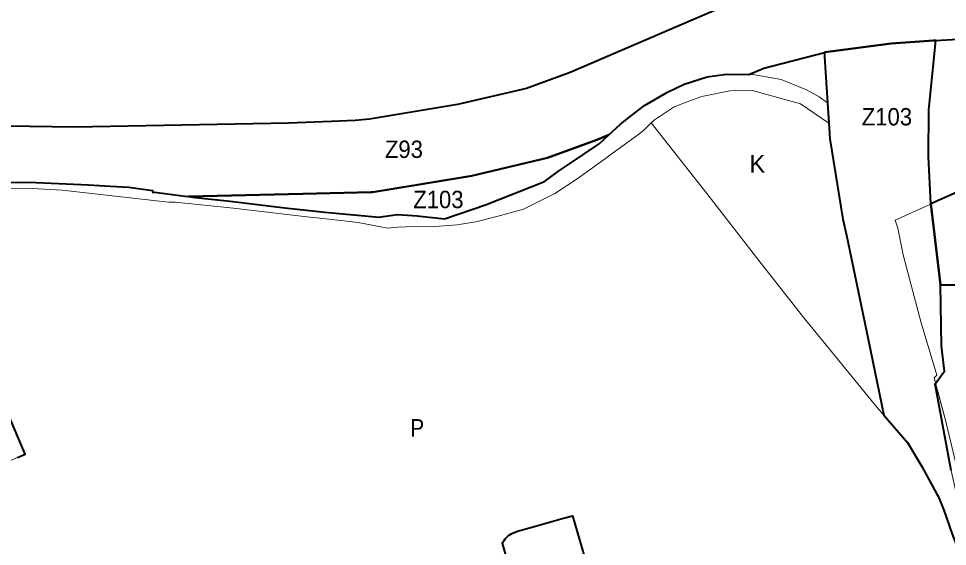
# Model space of a CAD drawing. Extents: x -650276 to -642489, y -1074425 to -1066658.
# Drawn here: x -649154 to -647871, y -1069752 to -1069023 of the extents above; entities that cross this region are included whole.
import ezdxf

# ---------------------------------------------------------------- set-up
doc = ezdxf.new("R2010")
doc.units = 0
doc.header["$LTSCALE"] = 9.6
for name, color, linetype, lineweight in [('1', 7, 'Continuous', 13), ('43', 7, 'Continuous', 13), ('44', 7, 'Continuous', 40), ('45', 7, 'Continuous', 40), ('47', 7, 'Continuous', 13), ('60', 7, 'Continuous', 35)]:
    doc.layers.add(name, color=color, linetype=linetype, lineweight=lineweight)

msp = doc.modelspace()

# ---------------------------------------------------------------- linework, layer by layer
at = {"layer": '1'}
for points in [[(-647858.44, -1069749.43), (-647875.82, -1069701.85), (-647883.51, -1069682.71), (-647885.34, -1069679.38), (-647906.16, -1069641.48), (-647925.99, -1069608.57), (-647967.53, -1069559.94), (-648068.71, -1069436.57), (-648127.77, -1069361.38), (-648203.01, -1069264.73), (-648280.1, -1069166.97), (-648290.39, -1069177.69), (-648298.85, -1069183.86), (-648338.87, -1069213.04), (-648342.93, -1069216), (-648352.75, -1069223.16), (-648381.96, -1069244.46), (-648412.97, -1069264.69), (-648456.09, -1069286.03), (-648493.11, -1069296.38), (-648522.23, -1069303.81), (-648547.96, -1069308.01), (-648578.69, -1069310.32), (-648618.32, -1069310.7), (-648629.16, -1069310.91), (-648643.83, -1069312.66), (-648684.39, -1069304.67), (-648724.82, -1069299.92), (-648741.58, -1069298.16), (-648755.56, -1069296.7), (-648856.68, -1069285.01), (-648937.2, -1069276.37), (-648945.96, -1069276.64), (-648959.11, -1069275.13), (-649093.48, -1069259.74), (-649142.11, -1069257.07), (-649181.7, -1069258.52)], [(-647858.37, -1069263.03), (-647942.68, -1069301.34), (-647939.14, -1069312.22), (-647931.96, -1069349.21), (-647920.91, -1069391.06), (-647906.89, -1069443.38), (-647885.3, -1069515.57), (-647889.22, -1069519.32), (-647873.43, -1069577.87), (-647852.44, -1069664.03)], [(-649184.1, -1069532.2), (-649144.57, -1069624.6), (-649241.11, -1069665.9)]]:
    msp.add_lwpolyline(points, dxfattribs=at)
at = {"layer": '44'}
for points in [[(-648156.739, -1068996.273), (-648392.002, -1069097.554), (-648451.865, -1069119.456), (-648547.243, -1069141.81), (-648668.959, -1069161.838), (-648688.912, -1069163.603), (-648721.315, -1069164.952), (-648781.015, -1069167.44), (-649076.02, -1069172.683), (-649169.781, -1069171.432)], [(-648040.456, -1069069.483), (-648039.666, -1069069.279), (-647948.18, -1069057.276)], [(-647948.18, -1069057.276), (-648039.666, -1069069.279), (-648040.456, -1069069.483)], [(-647948.18, -1069057.276), (-647889.927, -1069053.218), (-647886.615, -1069053.052)], [(-647886.615, -1069053.052), (-647889.927, -1069053.218), (-647948.18, -1069057.276)], [(-647887.087, -1069527.229), (-647878.73, -1069515.45), (-647874.75, -1069509.84), (-647878.93, -1069475.09), (-647880.326, -1069390.832), (-647893.553, -1069279.021), (-647896.67, -1069213.573), (-647896.362, -1069149.171), (-647886.615, -1069053.052)], [(-647886.615, -1069053.052), (-647856.541, -1069051.548), (-647756.441, -1069053.207), (-647708.401, -1069056.275), (-647511.94, -1069076.703), (-647426.417, -1069084.624), (-647344.902, -1069091.02), (-647270.522, -1069094.255), (-647197.498, -1069094.255), (-647123.648, -1069091.043), (-647065.688, -1069087.73)], [(-648665.007, -1069262.694), (-648527.693, -1069239.938), (-648423.173, -1069215.44), (-648354.978, -1069190.492), (-648338.523, -1069183.389), (-648322.14, -1069168.56), (-648306.83, -1069156.57), (-648289.25, -1069142.79), (-648257.5, -1069124.41), (-648234.22, -1069113.6), (-648202.46, -1069103.3), (-648175.65, -1069099.64), (-648144.866, -1069099.987), (-648124.327, -1069091.181), (-648040.705, -1069069.547), (-648040.456, -1069069.483)], [(-648040.456, -1069069.483), (-648040.537, -1069075.531), (-648036.291, -1069139.458), (-648034.421, -1069167.61)], [(-648034.421, -1069167.61), (-648033, -1069189), (-648015, -1069300), (-648010.092, -1069322.087), (-647980.331, -1069465.915), (-647958.34, -1069570.699), (-647925.99, -1069608.57)], [(-648526.15, -1069286.21), (-648508.95, -1069280.01), (-648427.08, -1069247.75), (-648407.73, -1069233.88), (-648389.91, -1069221.86), (-648355.81, -1069198.88), (-648351.77, -1069195.88), (-648338.523, -1069183.389), (-648354.978, -1069190.492)], [(-648354.978, -1069190.492), (-648423.173, -1069215.44), (-648527.693, -1069239.938), (-648652.716, -1069260.657)], [(-649165.62, -1069249.43), (-649139.63, -1069248.73), (-649056.95, -1069252.55), (-649026.955, -1069254.366), (-649001.3, -1069255.92), (-648968.49, -1069260.36), (-648968.05, -1069263.06), (-648965.8, -1069262.75), (-648937.91, -1069266.51), (-648924.13, -1069268.21), (-648918.889, -1069268.875)], [(-648918.889, -1069268.875), (-648761.189, -1069265.035), (-648666.827, -1069262.738), (-648665.007, -1069262.694)], [(-648666.827, -1069262.738), (-648761.189, -1069265.035), (-648918.889, -1069268.875), (-648909.86, -1069270.02), (-648861.49, -1069275.34), (-648785.92, -1069284.2), (-648730.66, -1069290.43), (-648730.66, -1069290.43), (-648655.53, -1069297.18), (-648650.06, -1069296.39), (-648636.85, -1069294.49)], [(-648652.716, -1069260.657), (-648665.007, -1069262.694), (-648666.827, -1069262.738)], [(-648636.85, -1069294.49), (-648630.82, -1069293.63), (-648609.425, -1069295.033), (-648603.228, -1069295.53), (-648565.18, -1069299.46), (-648526.15, -1069286.21)], [(-647865.69, -1069647.32), (-647887.649, -1069528.021), (-647887.087, -1069527.229)], [(-647925.99, -1069608.57), (-647906.16, -1069641.48), (-647885.665, -1069678.788), (-647885.663, -1069678.794), (-647883.51, -1069682.71), (-647875.82, -1069701.85)], [(-647875.82, -1069701.85), (-647864.19, -1069735.12), (-647858.44, -1069749.43), (-647852.63, -1069775.7), (-647850.66, -1069785.74), (-647849.165, -1069793.367), (-647843.74, -1069817.63), (-647841.402, -1069792.351)]]:
    msp.add_lwpolyline(points, dxfattribs=at)
msp.add_lwpolyline([(-647860.52, -1069390.72), (-647848.24, -1069390.65), (-647845.25, -1069390.07), (-647843.41, -1069389.23), (-647841.81, -1069387.99), (-647840.42, -1069386.51), (-647839.4, -1069384.73), (-647838.79, -1069382.86), (-647836.2, -1069362.68), (-647832.29, -1069338.58), (-647832.29, -1069338.58), (-647831.19, -1069320.69), (-647830.23, -1069305.38), (-647826.928, -1069253.199), (-647848.17, -1069259.21), (-647858.37, -1069263.03), (-647893.553, -1069279.017), (-647880.326, -1069390.832)], close=True, dxfattribs=at)
msp.add_arc((-648354.978, -1069190.492), 0.000000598, 264.13978, 298.69712, dxfattribs=at)
at = {"layer": '45'}
for points in [[(-649155.082, -1069629.097), (-649144.57, -1069624.6), (-649184.1, -1069532.2)], [(-648480.15, -1069765.358), (-648485.323, -1069747.432), (-648485.023, -1069746.592), (-648483.157, -1069743.818), (-648481.673, -1069741.612), (-648477.273, -1069737.482), (-648475.905, -1069736.566), (-648472.283, -1069734.142), (-648464.333, -1069730.932), (-648439.683, -1069724.232), (-648401.171, -1069713.196), (-648388.514, -1069709.779), (-648372.522, -1069765.283)]]:
    msp.add_lwpolyline(points, dxfattribs=at)
at = {"layer": '47'}
for points in [[(-648036.291, -1069139.458), (-648040.537, -1069075.531), (-648040.5, -1069072.79), (-648040.705, -1069069.548), (-648124.327, -1069091.181), (-648144.866, -1069099.987)], [(-648144.866, -1069099.987), (-648139.27, -1069100.05), (-648100.37, -1069107.1), (-648100.37, -1069107.1), (-648065.16, -1069121.12)], [(-648065.16, -1069121.12), (-648048.06, -1069130.81), (-648036.291, -1069139.458)]]:
    msp.add_lwpolyline(points, dxfattribs=at)
for points in [[(-648127.77, -1069361.38), (-648068.71, -1069436.57), (-647967.53, -1069559.94), (-647958.214, -1069571.3), (-647980.331, -1069465.915), (-648010.092, -1069322.087), (-648015, -1069300), (-648033, -1069189), (-648034.421, -1069167.61), (-648073.66, -1069140.86), (-648141.92, -1069121.66), (-648171.14, -1069122.83), (-648207.77, -1069129.95), (-648209.89, -1069130.36), (-648226.51, -1069136.57), (-648248.14, -1069144.65), (-648268.87, -1069158.61), (-648270.92, -1069159.99), (-648275.19, -1069162.87), (-648280.1, -1069166.97), (-648203.01, -1069264.73)], [(-647845.086, -1069748.753), (-647842.438, -1069760.647), (-647844.371, -1069761.991), (-647843.337, -1069769.013), (-647822.54, -1069759.29), (-647830, -1069744.7), (-647835.76, -1069730.01), (-647845.85, -1069691.2), (-647852.44, -1069664.03), (-647873.43, -1069577.87), (-647887.087, -1069527.229), (-647865.69, -1069647.32), (-647855.158, -1069695.232), (-647846.484, -1069736.663)]]:
    msp.add_lwpolyline(points, close=True, dxfattribs=at)

# ---------------------------------------------------------------- texts
at = {"layer": '43'}
msp.add_text('K', height=24, dxfattribs=at).set_placement((-648144.004, -1069235.577))
msp.add_text('K', height=24, dxfattribs=at).set_placement((-648144.004, -1069235.577))
at = {"layer": '44', "width": 0.95}
for s, p in [('Z103', (-647989.032, -1069170.515)), ('Z103', (-647989.032, -1069170.515)), ('Z93', (-648647.673, -1069215.426)), ('Z93', (-648647.673, -1069215.426)), ('Z103', (-648608.542, -1069284.81)), ('Z103', (-648608.542, -1069284.81))]:
    msp.add_text(s, height=24, dxfattribs=at).set_placement(p)
at = {"layer": '60', "width": 0.9}
msp.add_text('P', height=24, dxfattribs=at).set_placement((-648612.658, -1069600.244))

doc.saveas('drawing.dxf')
